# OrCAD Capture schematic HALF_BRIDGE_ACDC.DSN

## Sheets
1 PAGE2: size A; title: Half bridge ACDC converter; rev: 1.0
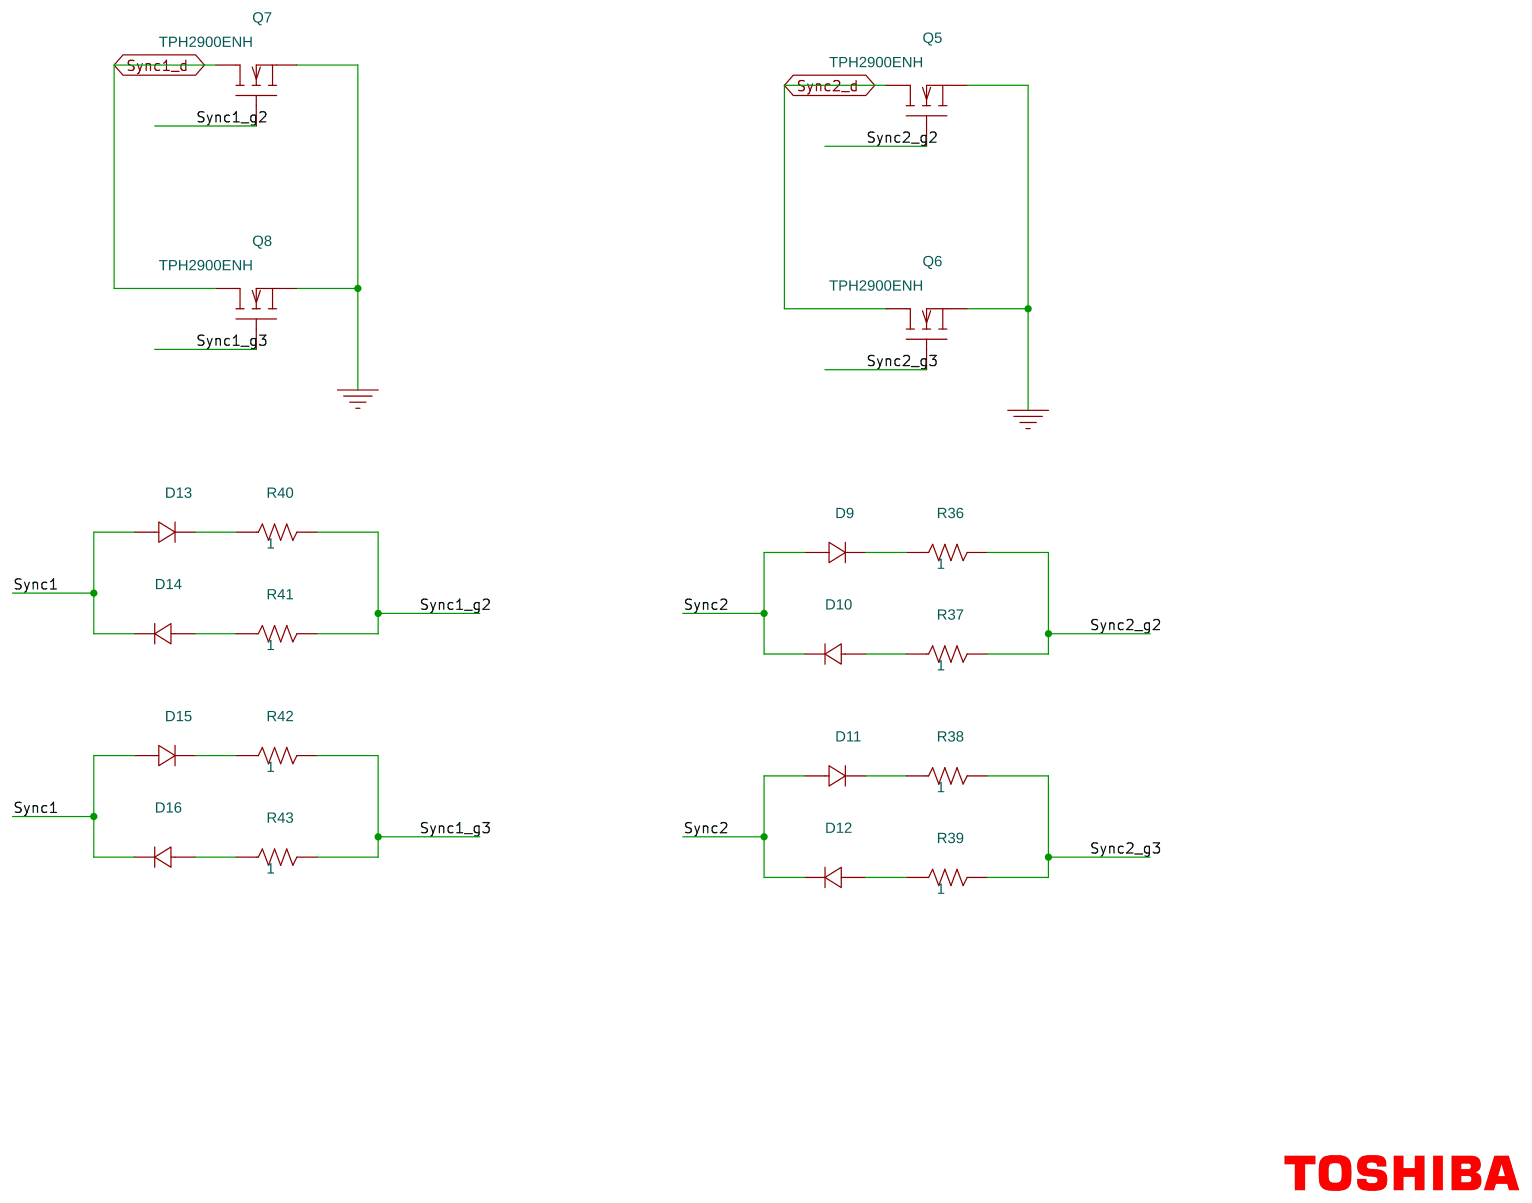
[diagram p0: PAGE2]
2 PAGE1: size A
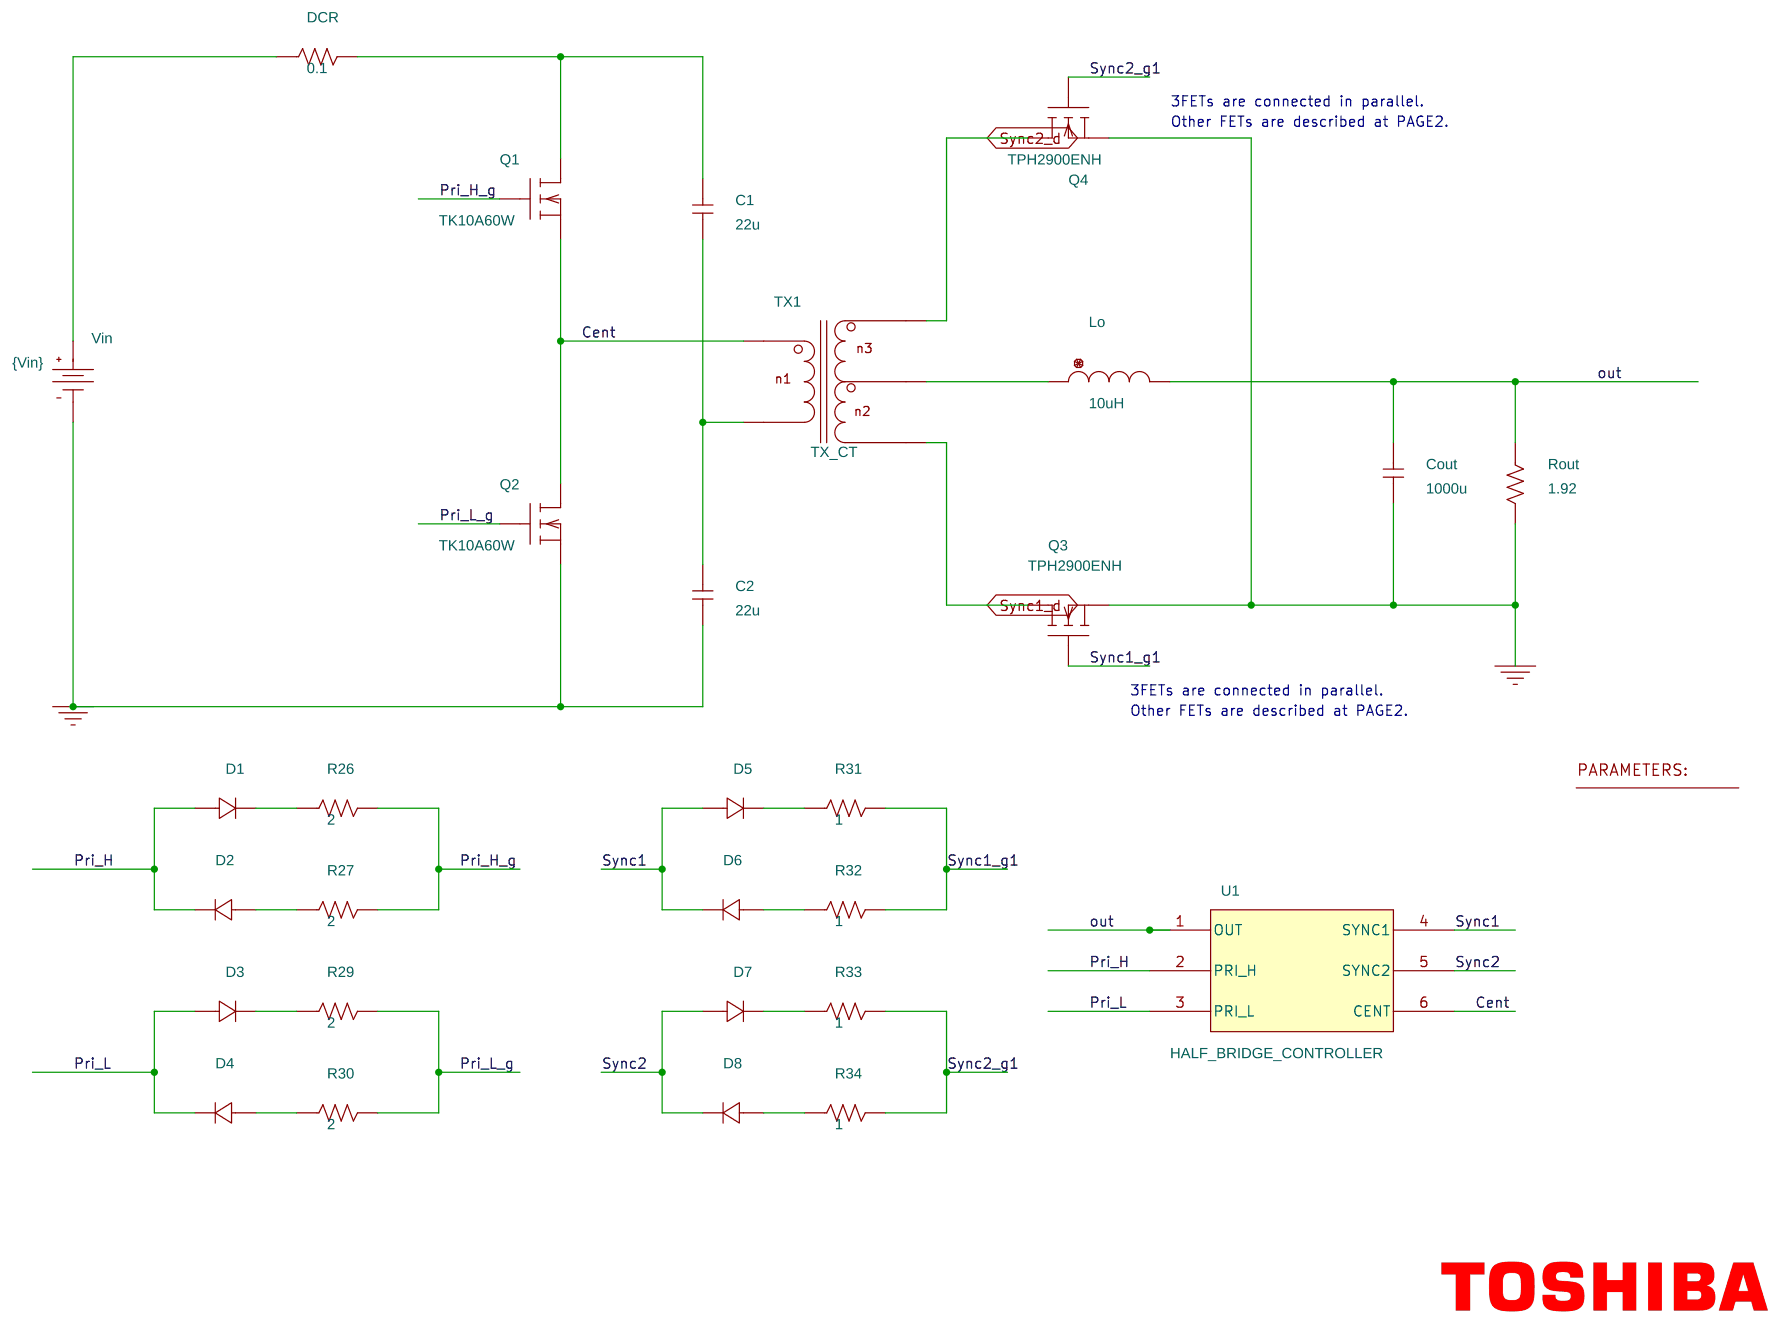
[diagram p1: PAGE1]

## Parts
sheet PAGE1
1  PARAM
C1  22u  [cap196]
C2  22u  [cap196]
Cout  1000u  [cap196]
D1  Diode_nom
D2  Diode_nom
D3  Diode_nom
D4  Diode_nom
D5  Diode_nom
D6  Diode_nom
D7  Diode_nom
D8  Diode_nom
DCR  0.1  [AXRC05]
Lo  10uH  [DISC350x175LS200x100034]
Q1  TK10A60W
Q2  TK10A60W
Q3  TPH2900ENH
Q4  TPH2900ENH
R26  2  [AXRC05]
R27  2  [AXRC05]
R29  2  [AXRC05]
R30  2  [AXRC05]
R31  1  [AXRC05]
R32  1  [AXRC05]
R33  1  [AXRC05]
R34  1  [AXRC05]
Rout  1.92  [AXRC05]
TX1  TX_CT
U1  HALF_BRIDGE_CONTROLLER
Vin  VDC
sheet PAGE2
D9  Diode_nom
D10  Diode_nom
D11  Diode_nom
D12  Diode_nom
D13  Diode_nom
D14  Diode_nom
D15  Diode_nom
D16  Diode_nom
Q5  TPH2900ENH
Q6  TPH2900ENH
Q7  TPH2900ENH
Q8  TPH2900ENH
R36  1  [AXRC05]
R37  1  [AXRC05]
R38  1  [AXRC05]
R39  1  [AXRC05]
R40  1  [AXRC05]
R41  1  [AXRC05]
R42  1  [AXRC05]
R43  1  [AXRC05]

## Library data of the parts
1 = PARAM: Fc: 100k; Rdrv_off_p: 2; Rdrv_off_s: 0.5; Rdrv_on_p: 5.8; Rdrv_on_s: 5; Td: 80n; Vdrv_p: 12; Vdrv_s: 12; Vin: 380; Vout: 24
C1 C2 Cout = C
D1-D16 = Diode_nom
DCR R26 R27 R29-R34 R36-R43 Rout = R
Lo = L
Q1 Q2 = TK10A60W
Q3-Q8 = TPH2900ENH
TX1 = TX_CT
U1 = HALF_BRIDGE_CONTROLLER
Vin = VDC: DC: {Vin}

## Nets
0: C2.2 Cout.2 Q2.0(s) Q3.0(s) Q4.0(s) Q5.0(s) Q6.0(s) Q7.0(s) Q8.0(s) Rout.2 Vin.1(-)
Cent: Q1.0(s) Q2.2(d) TX1.1 U1.6(CENT)
out: Cout.1 Lo.2 Rout.1 U1.1(OUT)
Pri_H: D1.0(1) D2.1(2) U1.2(PRI_H)
Pri_H_g: Q1.1(g) R26.2 R27.2
Pri_L: D3.0(1) D4.1(2) U1.3(PRI_L)
Pri_L_g: Q2.1(g) R29.2 R30.2
Sync1: D5.0(1) D6.1(2) U1.4(SYNC1)
Sync1 (page PAGE2): D13.0(1) D14.1(2) D15.0(1) D16.1(2)
Sync1_d: Q3.2(d) Q7.2(d) Q8.2(d) TX1.5
Sync1_g1: Q3.1(g) R31.2 R32.2
Sync1_g2: Q7.1(g) R40.2 R41.2
Sync1_g3: Q8.1(g) R42.2 R43.2
Sync2: D7.0(1) D8.1(2) U1.5(SYNC2)
Sync2 (page PAGE2): D9.0(1) D10.1(2) D11.0(1) D12.1(2)
Sync2_d: Q4.2(d) Q5.2(d) Q6.2(d) TX1.3
Sync2_g1: Q4.1(g) R33.2 R34.2
Sync2_g2: Q5.1(g) R36.2 R37.2
Sync2_g3: Q6.1(g) R38.2 R39.2
N2379572: DCR.1 Vin.0(+)
N2379578: C1.1 DCR.2 Q1.2(d)
N2379641: C1.2 C2.1 TX1.2
N2379769: D1.1(2) R26.1
N2379773: D2.0(1) R27.1
N2380920: D3.1(2) R29.1
N2380984: D4.0(1) R30.1
N2381401: D5.1(2) R31.1
N2381465: D6.0(1) R32.1
N2381641: D7.1(2) R33.1
N2381705: D8.0(1) R34.1
N2418237: D9.1(2) R36.1
N2418305: D10.0(1) R37.1
N2418518: D11.1(2) R38.1
N2418586: D12.0(1) R39.1
N2419479: D13.1(2) R40.1
N2419547: D14.0(1) R41.1
N2419595: D15.1(2) R42.1
N2419663: D16.0(1) R43.1
N13380831: Lo.1 TX1.4

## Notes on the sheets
sheet 2
- 3FETs are connected in parallel.
- Other FETs are described at PAGE2.
- 3FETs are connected in parallel.
- Other FETs are described at PAGE2.
